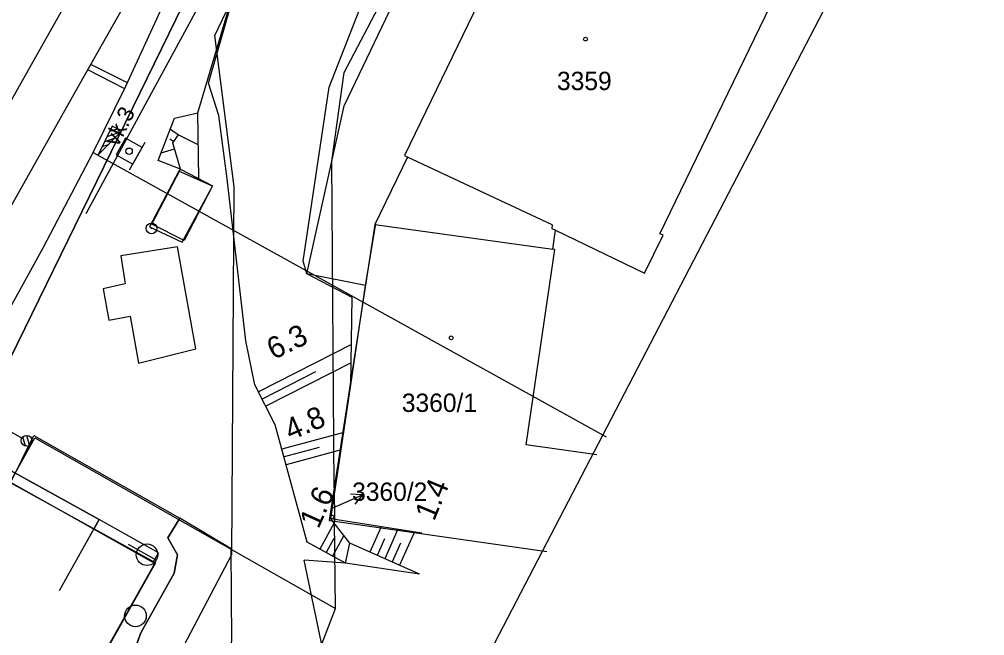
# Model space of a CAD drawing. Extents: x -781083 to -763634, y -1029516 to -1022695.
# Drawn here: x -765053 to -764963.8, y -1024056.2 to -1023999.1 of the extents above; entities that cross this region are included whole.
import ezdxf

# ---------------------------------------------------------------- set-up
doc = ezdxf.new("R2010")
doc.units = 0
for name, color, linetype in [('Default', 7, 'Continuous'), ('Hranice parcel', 7, 'Continuous'), ('Parcelní čísla', 7, 'Continuous'), ('Pop  PČ popisy', 7, 'Continuous'), ('PS120111-MOK', 7, 'Continuous'), ('PS_12-01-10_Kabelizace_nove_kabelizace', 7, 'Continuous'), ('PS_12-01-11_SZZ_Slany_rusene_prvky', 7, 'Continuous'), ('SO128401_EOV_trasa', 7, 'Continuous'), ('SO128602_NN_trasa', 7, 'Continuous'), ('Vnitřní kresba', 7, 'Continuous'), ('Vrstva 1', 7, 'Continuous'), ('Vrstva 16', 7, 'Continuous'), ('Vrstva 17', 7, 'Continuous'), ('Vrstva 23', 7, 'Continuous'), ('Vrstva 25', 7, 'Continuous'), ('Vrstva 3', 7, 'Continuous'), ('Vrstva 43', 7, 'Continuous'), ('Vrstva 48', 7, 'Continuous'), ('Vrstva 49', 7, 'Continuous'), ('Vrstva 50', 7, 'Continuous'), ('Vrstva 51', 7, 'Continuous'), ('Vrstva 7', 7, 'Continuous'), ('Značky budov', 7, 'Continuous'), ('ČD Telematika_TK', 7, 'Continuous')]:
    doc.layers.add(name, color=color, linetype=linetype)

# ---------------------------------------------------------------- blocks, each defined once
blk = doc.blocks.new('4.02')
at = {"layer": 'Značky budov'}
blk.add_circle((-0.07, 0.01), 1.75, dxfattribs=at)
blk = doc.blocks.new('C090')
at = {"layer": 'Vrstva 3'}
for p, q in [((8.87, 17.74), (-8.87, 17.74)), ((-8.87, 17.74), (-8.87, 0)), ((8.87, 0), (8.87, 17.74)), ((-14.78, 0), (14.78, 0)), ((-8.87, 0), (8.87, 0))]:
    blk.add_line(p, q, dxfattribs=at)
blk.add_circle((0.02, 8.88), 2.96, dxfattribs=at)
blk = doc.blocks.new('C669_3')
at = {"layer": 'Vrstva 25'}
for p, q in [((0, 5), (0.01, 40)), ((7, 40), (33, 40)), ((-4.78, -1.46), (1.44, 4.77)), ((-2.39, -4.37), (4.38, 2.4))]:
    blk.add_line(p, q, dxfattribs=at)
blk.add_circle((0, 0), 5, dxfattribs=at)
blk.add_circle((0, 0), 5, dxfattribs=at)
for centre, start, end in [((10, 40), 359.99986, 179.99986), ((20, 39.88), 179.29728, 0.70243)]:
    blk.add_arc(centre, 10, start, end, dxfattribs=at)
blk = doc.blocks.new('C137_3')
at = {"layer": 'Vrstva 43'}
blk.add_circle((0, 0), 10, dxfattribs=at)
blk = doc.blocks.new('C138_4')
at = {"layer": 'Vrstva 43'}
blk.add_line((0, 20), (0.01, -9.96), dxfattribs=at)
blk.add_circle((0, 0), 9.96, dxfattribs=at)
blk = doc.blocks.new('C053_6')
at = {"layer": 'Vrstva 50'}
blk.add_line((-0.5, -0.01), (0.5, 0.01), dxfattribs=at)
blk.add_circle((0, 0), 5, dxfattribs=at)
blk = doc.blocks.new('POINT_DISPLAY')
at = {"layer": 'Default'}
blk.add_line((0, 0), (0, 0), dxfattribs=at)
blk = doc.blocks.new('C335')
at = {"layer": 'Vrstva 7'}
blk.add_blockref('POINT_DISPLAY', (0, 0), dxfattribs=at)
blk = doc.blocks.new('C674')
at = {"layer": 'Vrstva 3'}
for p, q in [((-24.24, 5), (-29.49, 10.42)), ((-18.99, 5), (-28.44, 14.54)), ((-13.74, 5), (-20.52, 11.88)), ((-8.49, 5), (-12.77, 9.28)), ((-3.24, 5), (-5, 6.68))]:
    blk.add_line(p, q, dxfattribs=at)
blk.add_lwpolyline([(0, 5), (-29.49, 14.89), (-29.49, 5)], close=True, dxfattribs=at)
blk = doc.blocks.new('C090_3')
at = {"layer": 'PS_12-01-11_SZZ_Slany_rusene_prvky'}
for p, q in [((8.87, 17.74), (-8.87, 17.74)), ((-8.87, 17.74), (-8.87, 0)), ((8.87, 0), (8.87, 17.74)), ((-14.78, 0), (14.78, 0)), ((-8.87, 0), (8.87, 0))]:
    blk.add_line(p, q, dxfattribs=at)
blk.add_circle((0.02, 8.88), 2.96, dxfattribs=at)
blk = doc.blocks.new('C674_1')
at = {"layer": 'PS_12-01-11_SZZ_Slany_rusene_prvky'}
for p, q in [((-24.24, 5), (-29.49, 10.42)), ((-18.99, 5), (-28.44, 14.54)), ((-13.74, 5), (-20.52, 11.88)), ((-8.49, 5), (-12.77, 9.28)), ((-3.24, 5), (-5, 6.68))]:
    blk.add_line(p, q, dxfattribs=at)
blk.add_lwpolyline([(0, 5), (-29.49, 14.89), (-29.49, 5)], close=True, dxfattribs=at)
blk.add_lwpolyline([(0, 5), (-29.49, 14.89), (-29.49, 5)], close=True, dxfattribs=at)

msp = doc.modelspace()

# ---------------------------------------------------------------- linework, layer by layer
msp.add_lwpolyline([(-765336.117, -1024363.479), (-765204.05, -1024432.093), (-764769.725, -1023596.107), (-764901.792, -1023527.494)], close=True)
at = {"layer": 'Hranice parcel'}
for p, q in [((-765020.13, -1024018.12), (-765023.89, -1024042.47)), ((-765020.13, -1024018.12), (-765003.68, -1024020.39)), ((-765023.89, -1024042.47), (-765023.86, -1024045.56)), ((-765023.78, -1024053.63), (-765023.86, -1024045.56)), ((-765033.35, -1024078.65), (-765023.78, -1024053.63))]:
    msp.add_line(p, q, dxfattribs=at)
for points in [[(-765023.89, -1024042.47), (-765024.12, -1024012.25), (-765022.98, -1024004.05), (-765008.17, -1023975.85), (-765006.43, -1023973.28)], [(-765003.68, -1024020.39), (-765003.43, -1024018.64), (-764995.2, -1024022.62), (-764993.49, -1024019.1), (-764993.79, -1024018.96), (-764982.12, -1023994.83), (-765004.15, -1023984.35), (-765017.4, -1024011.74), (-765017.11, -1024011.88), (-765020.13, -1024018.12)], [(-764999.613, -1024039.42), (-765006.14, -1024038.49), (-765003.5, -1024020.42), (-765003.68, -1024020.39)], [(-765053.85, -1024041.95), (-765051.55, -1024037.85), (-765023.78, -1024053.63)], [(-765062.77, -1024089.18), (-765057.73, -1024080.2), (-765058.01, -1024080.04), (-765055.01, -1024074.69), (-765050.78, -1024077.07), (-765044.52, -1024065.9), (-765048.76, -1024063.56), (-765045.8, -1024058.29), (-765045.51, -1024058.45), (-765040.46, -1024049.46), (-765053.85, -1024041.95)], [(-765023.89, -1024042.47), (-765024.35, -1024045.49), (-765023.86, -1024045.56)], [(-765023.86, -1024045.56), (-765004.252, -1024048.35)]]:
    msp.add_lwpolyline(points, dxfattribs=at)
at = {"layer": 'Pop  PČ popisy'}
for p, q in [((-765024.02, -1024044.33), (-765021.278, -1024043.109)), ((-765021.278, -1024043.109), (-765022.397, -1024043.059)), ((-765021.278, -1024043.109), (-765021.99, -1024043.974)), ((-765024.03, -1024044.34), (-765024.02, -1024044.33))]:
    msp.add_line(p, q, dxfattribs=at)
at = {"layer": 'PS120111-MOK'}
msp.add_lwpolyline([(-765225.805, -1024328.474), (-765227.041, -1024327.403), (-765189.607, -1024263.284), (-765167.089, -1024223.521), (-765111.836, -1024124.939), (-765108.851, -1024119.501), (-765085.73, -1024077.899), (-765081.023, -1024080.523), (-765060.822, -1024044.042), (-765057.835, -1024038.647), (-765021.888, -1023965.037), (-765009.529, -1023945.01), (-764990.029, -1023909.994), (-764973.93, -1023884.565), (-764957.796, -1023847.878), (-764953.349, -1023837.037), (-764952.504, -1023834.976), (-764951.393, -1023835.06)], dxfattribs=at)
at = {"layer": 'PS_12-01-10_Kabelizace_nove_kabelizace'}
for points in [[(-764973.93, -1023884.565), (-764990.029, -1023909.994), (-765009.529, -1023945.01), (-765021.888, -1023965.037), (-765057.835, -1024038.647)], [(-765049.263, -1024051.977), (-765045.625, -1024045.395), (-765057.835, -1024038.647)]]:
    msp.add_lwpolyline(points, dxfattribs=at)
at = {"layer": 'SO128401_EOV_trasa'}
msp.add_lwpolyline([(-765060.824, -1024044.045), (-765057.835, -1024038.647), (-765021.888, -1023965.037), (-765009.529, -1023945.01), (-764990.029, -1023909.994), (-764973.93, -1023884.565), (-764973.93, -1023884.565), (-764957.796, -1023847.878), (-764957.796, -1023847.878), (-764953.349, -1023837.037), (-764953.349, -1023837.037), (-764952.595, -1023837.444), (-764952.595, -1023837.444), (-764952.595, -1023837.444), (-764952.595, -1023837.444)], dxfattribs=at)
at = {"layer": 'SO128602_NN_trasa'}
for points in [[(-765060.824, -1024044.045), (-765057.835, -1024038.647), (-765057.835, -1024038.647), (-765045.625, -1024045.395), (-765046.718, -1024047.371)], [(-765040.634, -1024049.362), (-765040.136, -1024048.474), (-765045.625, -1024045.395), (-765046.118, -1024046.286)]]:
    msp.add_lwpolyline(points, dxfattribs=at)
at = {"layer": 'Vnitřní kresba'}
for p, q in [((-765003.73, -1024018.13), (-765017.11, -1024011.88)), ((-765038.24, -1024013.17), (-765040.96, -1024018.32)), ((-765035.13, -1024014.56), (-765038.24, -1024013.17)), ((-765037.93, -1024019.73), (-765035.13, -1024014.56)), ((-765040.96, -1024018.32), (-765037.93, -1024019.73)), ((-765003.73, -1024018.13), (-765003.78, -1024018.47)), ((-765003.78, -1024018.47), (-765003.43, -1024018.64))]:
    msp.add_line(p, q, dxfattribs=at)
at = {"layer": 'Vrstva 1'}
for points in [[(-765132.595, -1024166.323), (-765129.154, -1024160.282), (-765120.123, -1024144.179), (-765113.641, -1024132.601), (-765108.378, -1024123.125), (-765107.852, -1024122.175), (-765106.668, -1024120.081), (-765061.822, -1024040.141), (-765060.629, -1024038.009), (-765057.197, -1024031.875), (-765051.942, -1024022.391), (-765050.753, -1024020.205), (-765046.155, -1024011.44), (-765043.134, -1024005.303), (-765039.745, -1023997.951), (-765035.047, -1023987.211), (-765027.653, -1023970.046)], [(-765138.578, -1024157.675), (-765133.719, -1024149), (-765131.846, -1024145.662), (-765126.088, -1024135.402), (-765117.89, -1024120.799), (-765116.125, -1024117.657), (-765114.927, -1024115.52), (-765098.436, -1024086.158), (-765092.138, -1024074.961), (-765090.925, -1024072.798), (-765083.437, -1024059.463), (-765075.468, -1024045.285), (-765069.982, -1024035.533), (-765068.774, -1024033.384), (-765060.064, -1024017.884), (-765058.869, -1024015.756), (-765052.709, -1024004.781), (-765046.025, -1023992.89)], [(-765173.904, -1024229.916), (-765173.254, -1024228.763), (-765165.873, -1024215.668), (-765157.715, -1024201.193), (-765150.799, -1024188.931), (-765144.602, -1024177.925), (-765137.347, -1024165.014), (-765128.994, -1024150.127), (-765120.916, -1024135.756), (-765114.604, -1024124.554), (-765112.054, -1024120.015), (-765110.861, -1024117.895), (-765104.54, -1024106.641), (-765100.051, -1024098.661), (-765087.977, -1024077.275), (-765086.765, -1024075.13), (-765078.232, -1024059.989), (-765070.151, -1024045.656), (-765065.795, -1024037.884), (-765064.623, -1024035.796), (-765055.87, -1024020.2), (-765054.667, -1024018.056), (-765047.51, -1024005.326), (-765040.997, -1023993.749)]]:
    msp.add_lwpolyline(points, dxfattribs=at)
at = {"layer": 'Vrstva 16'}
msp.add_lwpolyline([(-765053.817, -1024042.01), (-765051.655, -1024037.645), (-765038.17, -1024045.277), (-765039.256, -1024047.109), (-765038.382, -1024048.675), (-765038.664, -1024050.369), (-765041.755, -1024055.876), (-765042.667, -1024058.341), (-765042.757, -1024060.558), (-765044.415, -1024065.882)], dxfattribs=at)
at = {"layer": 'Vrstva 17'}
for points in [[(-765022.971, -1024007.119), (-765006.143, -1023971.948), (-764997.137, -1023957.831), (-764990.499, -1023960.327), (-764988.733, -1023953.243), (-764969.021, -1023914.394)], [(-765036.387, -1024013.818), (-765036.485, -1024007.769), (-765030.419, -1023987.307), (-765020.565, -1023965.71), (-765004.95, -1023939.768)], [(-765021, -1024023.751), (-765026.405, -1024022.681), (-765022.971, -1024007.119)], [(-765024.701, -1024080.161), (-765033.331, -1024078.534), (-765028.371, -1024065.849), (-765024.795, -1024058.182), (-765026.659, -1024049.161)], [(-765016.013, -1024050.455), (-765022.847, -1024049.441), (-765026.659, -1024049.161)]]:
    msp.add_lwpolyline(points, dxfattribs=at)
at = {"layer": 'Vrstva 23'}
for points in [[(-765037.761, -1024019.603), (-765040.743, -1024018.089), (-765038.108, -1024013.004), (-765035.136, -1024014.523), (-765037.761, -1024019.603)], [(-765015.781, -1024046.651), (-765024.19, -1024045.354), (-765022.349, -1024032.951), (-765021, -1024023.751), (-765020.055, -1024018.041)], [(-765041.99, -1024030.935), (-765036.691, -1024029.626), (-765038.371, -1024020.185), (-765043.594, -1024021), (-765043.194, -1024023.614), (-765045.253, -1024024.074), (-765044.706, -1024026.976), (-765042.741, -1024026.606), (-765041.99, -1024030.935)], [(-765040.408, -1024049.421), (-765053.817, -1024042.01), (-765058.72, -1024050.836), (-765056.175, -1024052.261), (-765068.487, -1024074.264), (-765071.098, -1024072.598), (-765071.581, -1024073.57), (-765072.898, -1024072.876), (-765075.517, -1024077.649)], [(-765040.408, -1024049.421), (-765045.455, -1024058.42)]]:
    msp.add_lwpolyline(points, dxfattribs=at)
at = {"layer": 'Vrstva 3'}
msp.add_line((-765046.155, -1024011.44), (-764998.741, -1024037.742), dxfattribs=at)
at = {"layer": 'Vrstva 48'}
for p, q in [((-765039.031, -1024009.293), (-765038.282, -1024009.821)), ((-765039.07, -1024010.181), (-765038.713, -1024010.433)), ((-765039.869, -1024011.47), (-765038.637, -1024011.124)), ((-765022.29, -1024029.202), (-765030.89, -1024033.597)), ((-765022.317, -1024030.898), (-765030.209, -1024034.93)), ((-765025.602, -1024031.735), (-765030.55, -1024034.264)), ((-765023, -1024037.338), (-765028.721, -1024038.895)), ((-765025.282, -1024038.736), (-765028.524, -1024039.618)), ((-765023.241, -1024038.958), (-765028.327, -1024040.342)), ((-765023.901, -1024045.724), (-765025.223, -1024048.142)), ((-765019.55, -1024046.07), (-765020.594, -1024048.414)), ((-765018.013, -1024046.307), (-765019.224, -1024049.025)), ((-765023.923, -1024047.166), (-765024.633, -1024048.465)), ((-765022.998, -1024046.877), (-765024.043, -1024048.787)), ((-765019.233, -1024047.201), (-765019.909, -1024048.719)), ((-765016.477, -1024046.544), (-765017.854, -1024049.635)), ((-765017.763, -1024047.587), (-765018.539, -1024049.33))]:
    msp.add_line(p, q, dxfattribs=at)
at = {"layer": 'Vrstva 49'}
for points in [[(-765035.519, -1024005.026), (-765030.419, -1023987.307), (-765020.565, -1023965.71), (-765004.95, -1023939.768)], [(-765024.19, -1024045.354), (-765022.349, -1024032.951), (-765022.222, -1024024.871), (-765026.405, -1024022.681), (-765026.755, -1024021.515), (-765024.365, -1024005.419), (-765021.535, -1023998.172)], [(-765032.051, -1024028.868), (-765033.778, -1024013.895), (-765034.548, -1024008.03), (-765035.519, -1024005.026)], [(-765040.149, -1024012.199), (-765038.64, -1024008.277), (-765036.485, -1024007.769)], [(-765038.108, -1024013.004), (-765038.798, -1024010.553), (-765038.282, -1024009.821)], [(-765038.282, -1024009.821), (-765036.554, -1024010.675)], [(-765038.108, -1024013.004), (-765040.149, -1024012.199)], [(-765022.847, -1024049.441), (-765026.377, -1024047.511), (-765029.333, -1024036.645), (-765031.219, -1024032.954), (-765032.051, -1024028.868)], [(-765015.781, -1024046.651), (-765024.19, -1024045.354)], [(-765016.013, -1024050.455), (-765022.438, -1024047.593), (-765024.19, -1024045.354)], [(-765022.847, -1024049.441), (-765022.438, -1024047.593)]]:
    msp.add_lwpolyline(points, dxfattribs=at)
at = {"layer": 'Vrstva 51'}
for points in [[(-765042.757, -1024060.558), (-765042.667, -1024058.341), (-765041.755, -1024055.876), (-765038.664, -1024050.369), (-765038.382, -1024048.675), (-765039.256, -1024047.109), (-765038.17, -1024045.277)], [(-765026.41, -1024084.396), (-765033.851, -1024082.876), (-765037.195, -1024080.533), (-765037.729, -1024076.949), (-765033.356, -1024056.622), (-765033.425, -1024048.126), (-765038.17, -1024045.277)]]:
    msp.add_lwpolyline(points, dxfattribs=at)
at = {"layer": 'Vrstva 7'}
for p, q in [((-765043.001, -1024005.014), (-765046.367, -1024003.295)), ((-765043.252, -1024005.559), (-765046.662, -1024003.818))]:
    msp.add_line(p, q, dxfattribs=at)
at = {"layer": 'ČD Telematika_TK'}
for points in [[(-765046.807, -1024017.08), (-765029.13, -1023984.48), (-765018.689, -1023963.431), (-765009.158, -1023943.676), (-764986.584, -1023911.367), (-764975.521, -1023895.82), (-764979.204, -1023891.861), (-764970.396, -1023879.031), (-764960.103, -1023856.143), (-764944.124, -1023819.068), (-764943.31, -1023819.61)], [(-765257.028, -1024404.569), (-765256.037, -1024398.213), (-765249.421, -1024374.188), (-765226.425, -1024328.292), (-765185.224, -1024255.545), (-765167.149, -1024223.486), (-765171.928, -1024220.746), (-765141.483, -1024166.52), (-765136.718, -1024169.454), (-765086.954, -1024080.425), (-765063.726, -1024094.284), (-765054.277, -1024080.444), (-765052.94, -1024078.307), (-765049.809, -1024079.983), (-765033.351, -1024048.633), (-765033.134, -1024014.623), (-765034.915, -1024000.619), (-765019.65, -1023968.646), (-765007.996, -1023946.352)]]:
    msp.add_lwpolyline(points, dxfattribs=at)

# ---------------------------------------------------------------- block references
at = {"layer": 'PS_12-01-11_SZZ_Slany_rusene_prvky'}
for name, p, xscale, yscale, rotation in [('C674_1', (-765046.155, -1024011.44), 0.1, 0.10000000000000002, -116.20918138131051), ('C090_3', (-765042.069, -1024011.769), 0.10000000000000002, 0.10000000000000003, 60.69996012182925)]:
    msp.add_blockref(name, p, dxfattribs=dict(at, xscale=xscale, yscale=yscale, rotation=rotation))
at = {"layer": 'Vrstva 25', "xscale": 0.10000000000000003, "yscale": 0.1, "rotation": 60.699960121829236}
msp.add_blockref('C669_3', (-765052.313, -1024038.116), dxfattribs=at)
at = {"layer": 'Vrstva 3'}
for name, p, xscale, yscale, rotation in [('C674', (-765046.155, -1024011.44), 0.1, 0.10000000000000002, -116.20918138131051), ('C090', (-765042.069, -1024011.769), 0.10000000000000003, 0.1, 60.699960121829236)]:
    msp.add_blockref(name, p, dxfattribs=dict(at, xscale=xscale, yscale=yscale, rotation=rotation))
at = {"layer": 'Vrstva 43', "xscale": 0.10000000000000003, "yscale": 0.1, "rotation": 60.699960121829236}
for name, p in [('C138_4', (-765041.187, -1024048.663)), ('C137_3', (-765042.258, -1024054.32))]:
    msp.add_blockref(name, p, dxfattribs=at)
at = {"layer": 'Vrstva 50', "xscale": 0.10000000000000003, "yscale": 0.1, "rotation": 60.699960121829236}
msp.add_blockref('C053_6', (-765040.774, -1024018.475), dxfattribs=at)
at = {"layer": 'Vrstva 7', "xscale": 0.10000000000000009, "yscale": 0.10000000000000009, "rotation": 90}
msp.add_blockref('C335', (-765044.825, -1024004.419), dxfattribs=at)
at = {"layer": 'Značky budov', "xscale": 0.1, "yscale": 0.10000000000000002}
for p in [(-765000.66, -1024000.96), (-765013.07, -1024028.6), (-765024.09, -1024045.17)]:
    msp.add_blockref('4.02', p, dxfattribs=at)

# ---------------------------------------------------------------- texts
at = {"layer": 'Parcelní čísla'}
for s, p in [('3359', (-765003.3, -1024005.68)), ('3360/1', (-765017.64, -1024035.45)), ('3360/2', (-765022.233, -1024043.68))]:
    msp.add_text(s, height=1.7, dxfattribs=at).set_placement(p)
at = {"layer": 'Vrstva 3'}
msp.add_text('vk.3', height=1.5, rotation=63.79082, dxfattribs=at).set_placement((-765043.877, -1024011.003))
at = {"layer": 'Vrstva 48'}
for s, rotation, p in [('6.3', 25.88114, (-765029.498, -1024030.655)), ('4.8', 23.47323, (-765027.928, -1024038.136)), ('1.4', 67.40125, (-765014.662, -1024045.622)), ('1.6', 65.69985, (-765025.351, -1024046.345))]:
    msp.add_text(s, height=2, rotation=rotation, dxfattribs=at).set_placement(p)

doc.saveas('drawing.dxf')
